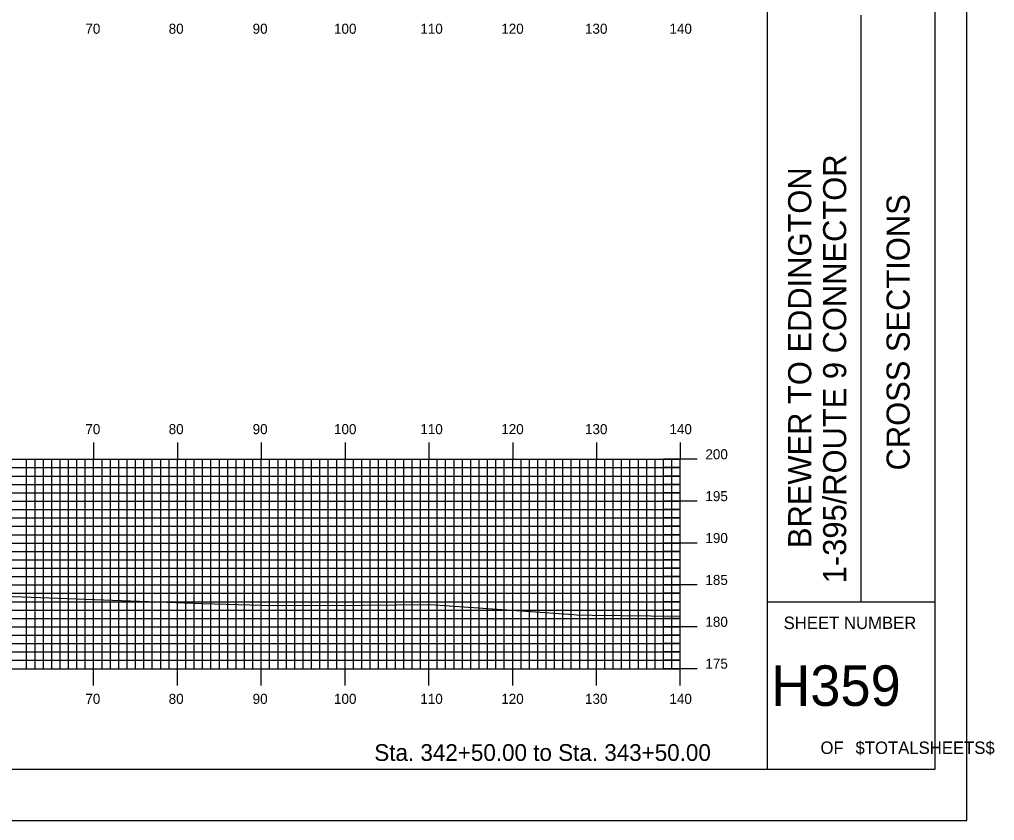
# Model space of a CAD drawing. Extents: x 1825147 to 1825490, y 442591 to 442811.
# Drawn here: x 1825373.5 to 1825489.9, y 442590.5 to 442686.2 of the extents above; entities that cross this region are included whole.
import ezdxf

# ---------------------------------------------------------------- set-up
doc = ezdxf.new("R2010")
doc.units = 0
for name, color, linetype in [('BORDER', 7, 'Continuous'), ('H_V ANNOTATION', 7, 'Continuous'), ('MAJOR', 7, 'Continuous'), ('MINOR', 7, 'Continuous'), ('PLOT BOUNDARY', 7, 'Continuous'), ('S_Roadway_Centerline', 7, 'Continuous')]:
    doc.layers.add(name, color=color, linetype=linetype)

msp = doc.modelspace()

# ---------------------------------------------------------------- linework, layer by layer
at = {"layer": 'BORDER'}
for p, q in [((1825462.76, 442596.67), (1825462.76, 442806.67)), ((1825473.94, 442616.67), (1825473.94, 442686.67)), ((1825462.76, 442616.67), (1825482.76, 442616.67))]:
    msp.add_line(p, q, dxfattribs=at)
msp.add_lwpolyline([(1825162.76, 442596.67), (1825482.76, 442596.67), (1825482.76, 442806.67), (1825162.76, 442806.67)], close=True, dxfattribs=at)
at = {"layer": 'MAJOR'}
for p, q in [((1825382.36, 442635.67), (1825382.36, 442633.67)), ((1825392.36, 442635.67), (1825392.36, 442633.67)), ((1825402.36, 442635.67), (1825402.36, 442633.67)), ((1825412.36, 442635.67), (1825412.36, 442633.67)), ((1825422.36, 442635.67), (1825422.36, 442633.67)), ((1825432.36, 442635.67), (1825432.36, 442633.67)), ((1825442.36, 442635.67), (1825442.36, 442633.67)), ((1825452.36, 442635.67), (1825452.36, 442633.67)), ((1825172.36, 442633.67), (1825452.36, 442633.67)), ((1825172.36, 442633.67), (1825452.36, 442633.67)), ((1825382.36, 442608.67), (1825382.36, 442633.67)), ((1825392.36, 442608.67), (1825392.36, 442633.67)), ((1825402.36, 442608.67), (1825402.36, 442633.67)), ((1825412.36, 442608.67), (1825412.36, 442633.67)), ((1825422.36, 442608.67), (1825422.36, 442633.67)), ((1825432.36, 442608.67), (1825432.36, 442633.67)), ((1825442.36, 442608.67), (1825442.36, 442633.67)), ((1825454.37, 442633.67), (1825450.36, 442633.67)), ((1825452.36, 442608.67), (1825452.36, 442633.67)), ((1825452.36, 442608.67), (1825452.36, 442633.67)), ((1825172.36, 442628.67), (1825452.36, 442628.67)), ((1825454.37, 442628.67), (1825450.36, 442628.67)), ((1825172.36, 442623.67), (1825452.36, 442623.67)), ((1825454.37, 442623.67), (1825450.36, 442623.67)), ((1825172.36, 442618.67), (1825452.36, 442618.67)), ((1825454.37, 442618.67), (1825450.36, 442618.67)), ((1825172.36, 442613.67), (1825452.36, 442613.67)), ((1825454.37, 442613.67), (1825450.36, 442613.67)), ((1825172.36, 442608.67), (1825452.36, 442608.67)), ((1825172.36, 442608.67), (1825452.36, 442608.67)), ((1825382.36, 442606.66), (1825382.36, 442608.67)), ((1825392.36, 442606.66), (1825392.36, 442608.67)), ((1825402.36, 442606.66), (1825402.36, 442608.67)), ((1825412.36, 442606.66), (1825412.36, 442608.67)), ((1825422.36, 442606.66), (1825422.36, 442608.67)), ((1825432.36, 442606.66), (1825432.36, 442608.67)), ((1825442.36, 442606.66), (1825442.36, 442608.67)), ((1825454.37, 442608.67), (1825450.36, 442608.67)), ((1825452.36, 442606.66), (1825452.36, 442608.67))]:
    msp.add_line(p, q, dxfattribs=at)
at = {"layer": 'MINOR'}
for p, q in [((1825374.36, 442608.67), (1825374.36, 442633.67)), ((1825375.36, 442608.67), (1825375.36, 442633.67)), ((1825376.36, 442608.67), (1825376.36, 442633.67)), ((1825377.36, 442608.67), (1825377.36, 442633.67)), ((1825378.36, 442608.67), (1825378.36, 442633.67)), ((1825379.36, 442608.67), (1825379.36, 442633.67)), ((1825380.36, 442608.67), (1825380.36, 442633.67)), ((1825381.36, 442608.67), (1825381.36, 442633.67)), ((1825383.36, 442608.67), (1825383.36, 442633.67)), ((1825384.36, 442608.67), (1825384.36, 442633.67)), ((1825385.36, 442608.67), (1825385.36, 442633.67)), ((1825386.36, 442608.67), (1825386.36, 442633.67)), ((1825387.36, 442608.67), (1825387.36, 442633.67)), ((1825388.36, 442608.67), (1825388.36, 442633.67)), ((1825389.36, 442608.67), (1825389.36, 442633.67)), ((1825390.36, 442608.67), (1825390.36, 442633.67)), ((1825391.36, 442608.67), (1825391.36, 442633.67)), ((1825393.36, 442608.67), (1825393.36, 442633.67)), ((1825394.36, 442608.67), (1825394.36, 442633.67)), ((1825395.36, 442608.67), (1825395.36, 442633.67)), ((1825396.36, 442608.67), (1825396.36, 442633.67)), ((1825397.36, 442608.67), (1825397.36, 442633.67)), ((1825398.36, 442608.67), (1825398.36, 442633.67)), ((1825399.36, 442608.67), (1825399.36, 442633.67)), ((1825400.36, 442608.67), (1825400.36, 442633.67)), ((1825401.36, 442608.67), (1825401.36, 442633.67)), ((1825403.36, 442608.67), (1825403.36, 442633.67)), ((1825404.36, 442608.67), (1825404.36, 442633.67)), ((1825405.36, 442608.67), (1825405.36, 442633.67)), ((1825406.36, 442608.67), (1825406.36, 442633.67)), ((1825407.36, 442608.67), (1825407.36, 442633.67)), ((1825408.36, 442608.67), (1825408.36, 442633.67)), ((1825409.36, 442608.67), (1825409.36, 442633.67)), ((1825410.36, 442608.67), (1825410.36, 442633.67)), ((1825411.36, 442608.67), (1825411.36, 442633.67)), ((1825413.36, 442608.67), (1825413.36, 442633.67)), ((1825414.36, 442608.67), (1825414.36, 442633.67)), ((1825415.36, 442608.67), (1825415.36, 442633.67)), ((1825416.36, 442608.67), (1825416.36, 442633.67)), ((1825417.36, 442608.67), (1825417.36, 442633.67)), ((1825418.36, 442608.67), (1825418.36, 442633.67)), ((1825419.36, 442608.67), (1825419.36, 442633.67)), ((1825420.36, 442608.67), (1825420.36, 442633.67)), ((1825421.36, 442608.67), (1825421.36, 442633.67)), ((1825423.36, 442608.67), (1825423.36, 442633.67)), ((1825424.36, 442608.67), (1825424.36, 442633.67)), ((1825425.36, 442608.67), (1825425.36, 442633.67)), ((1825426.36, 442608.67), (1825426.36, 442633.67)), ((1825427.36, 442608.67), (1825427.36, 442633.67)), ((1825428.36, 442608.67), (1825428.36, 442633.67)), ((1825429.36, 442608.67), (1825429.36, 442633.67)), ((1825430.36, 442608.67), (1825430.36, 442633.67)), ((1825431.36, 442608.67), (1825431.36, 442633.67)), ((1825433.36, 442608.67), (1825433.36, 442633.67)), ((1825434.36, 442608.67), (1825434.36, 442633.67)), ((1825435.36, 442608.67), (1825435.36, 442633.67)), ((1825436.36, 442608.67), (1825436.36, 442633.67)), ((1825437.36, 442608.67), (1825437.36, 442633.67)), ((1825438.36, 442608.67), (1825438.36, 442633.67)), ((1825439.36, 442608.67), (1825439.36, 442633.67)), ((1825440.36, 442608.67), (1825440.36, 442633.67)), ((1825441.36, 442608.67), (1825441.36, 442633.67)), ((1825443.36, 442608.67), (1825443.36, 442633.67)), ((1825444.36, 442608.67), (1825444.36, 442633.67)), ((1825445.36, 442608.67), (1825445.36, 442633.67)), ((1825446.36, 442608.67), (1825446.36, 442633.67)), ((1825447.36, 442608.67), (1825447.36, 442633.67)), ((1825448.36, 442608.67), (1825448.36, 442633.67)), ((1825449.36, 442608.67), (1825449.36, 442633.67)), ((1825450.36, 442608.67), (1825450.36, 442633.67)), ((1825451.36, 442608.67), (1825451.36, 442633.67)), ((1825172.36, 442632.67), (1825452.36, 442632.67)), ((1825452.36, 442632.67), (1825450.36, 442632.67)), ((1825172.36, 442631.67), (1825452.36, 442631.67)), ((1825452.36, 442631.67), (1825450.36, 442631.67)), ((1825172.36, 442630.67), (1825452.36, 442630.67)), ((1825452.36, 442630.67), (1825450.36, 442630.67)), ((1825172.36, 442629.67), (1825452.36, 442629.67)), ((1825452.36, 442629.67), (1825450.36, 442629.67)), ((1825172.36, 442627.67), (1825452.36, 442627.67)), ((1825452.36, 442627.67), (1825450.36, 442627.67)), ((1825172.36, 442626.67), (1825452.36, 442626.67)), ((1825452.36, 442626.67), (1825450.36, 442626.67)), ((1825172.36, 442625.67), (1825452.36, 442625.67)), ((1825452.36, 442625.67), (1825450.36, 442625.67)), ((1825172.36, 442624.67), (1825452.36, 442624.67)), ((1825452.36, 442624.67), (1825450.36, 442624.67)), ((1825172.36, 442622.67), (1825452.36, 442622.67)), ((1825452.36, 442622.67), (1825450.36, 442622.67)), ((1825172.36, 442621.67), (1825452.36, 442621.67)), ((1825172.36, 442620.67), (1825452.36, 442620.67)), ((1825452.36, 442621.67), (1825450.36, 442621.67)), ((1825452.36, 442620.67), (1825450.36, 442620.67)), ((1825172.36, 442619.67), (1825452.36, 442619.67)), ((1825452.36, 442619.67), (1825450.36, 442619.67)), ((1825172.36, 442617.67), (1825452.36, 442617.67)), ((1825452.36, 442617.67), (1825450.36, 442617.67)), ((1825172.36, 442616.67), (1825452.36, 442616.67)), ((1825452.36, 442616.67), (1825450.36, 442616.67)), ((1825172.36, 442615.67), (1825452.36, 442615.67)), ((1825452.36, 442615.67), (1825450.36, 442615.67)), ((1825172.36, 442614.67), (1825452.36, 442614.67)), ((1825452.36, 442614.67), (1825450.36, 442614.67)), ((1825172.36, 442612.67), (1825452.36, 442612.67)), ((1825452.36, 442612.67), (1825450.36, 442612.67)), ((1825172.36, 442611.67), (1825452.36, 442611.67)), ((1825452.36, 442611.67), (1825450.36, 442611.67)), ((1825172.36, 442610.67), (1825452.36, 442610.67)), ((1825452.36, 442610.67), (1825450.36, 442610.67)), ((1825172.36, 442609.67), (1825452.36, 442609.67)), ((1825452.36, 442609.67), (1825450.36, 442609.67))]:
    msp.add_line(p, q, dxfattribs=at)
at = {"layer": 'PLOT BOUNDARY'}
msp.add_lwpolyline([(1825146.57, 442590.55), (1825486.57, 442590.55), (1825486.57, 442810.55), (1825146.57, 442810.55)], close=True, dxfattribs=at)
at = {"layer": 'S_Roadway_Centerline'}
msp.add_lwpolyline([(1825364.09, 442617.59), (1825395.4, 442616.46), (1825402.38, 442616.27), (1825410.39, 442616.21), (1825422.56, 442616.35), (1825439.61, 442615.14), (1825439.99, 442615.12), (1825441.86, 442615.08), (1825452.36, 442614.93)], dxfattribs=at)

# ---------------------------------------------------------------- texts
at = {"layer": 'BORDER'}
for s, p in [('1-395/ROUTE 9 CONNECTOR', (1825472.16, 442618.87)), ('BREWER TO EDDINGTON', (1825467.99, 442623.07)), ('CROSS SECTIONS', (1825479.73, 442632.34))]:
    msp.add_text(s, height=2.7557, rotation=90, dxfattribs=at).set_placement(p)
for s, height, p in [('SHEET NUMBER', 1.4905, (1825464.69, 442613.4)), ('H359', 4.839, (1825463.2, 442604.23)), ('OF', 1.491, (1825469.09, 442598.49)), ('$TOTALSHEETS$', 1.4905, (1825473.27, 442598.49))]:
    msp.add_text(s, height=height, dxfattribs=at).set_placement(p)
at = {"layer": 'H_V ANNOTATION'}
for s, height, p in [('70', 1.2, (1825381.37, 442684.47)), ('80', 1.2, (1825391.31, 442684.47)), ('90', 1.2, (1825401.33, 442684.47)), ('100', 1.2, (1825411.04, 442684.47)), ('110', 1.2, (1825421.34, 442684.47)), ('120', 1.2, (1825431, 442684.47)), ('130', 1.2, (1825440.99, 442684.47)), ('140', 1.2, (1825451.07, 442684.47)), ('70', 1.2, (1825381.37, 442636.67)), ('80', 1.2, (1825391.31, 442636.67)), ('90', 1.2, (1825401.33, 442636.67)), ('100', 1.2, (1825411.04, 442636.67)), ('110', 1.2, (1825421.34, 442636.67)), ('120', 1.2, (1825431, 442636.67)), ('130', 1.2, (1825440.99, 442636.67)), ('140', 1.2, (1825451.07, 442636.67)), ('200', 1.2, (1825455.36, 442633.67)), ('195', 1.2, (1825455.36, 442628.67)), ('190', 1.2, (1825455.36, 442623.67)), ('185', 1.2, (1825455.36, 442618.67)), ('180', 1.2, (1825455.36, 442613.67)), ('175', 1.2, (1825455.36, 442608.67)), ('70', 1.2, (1825381.37, 442604.47)), ('80', 1.2, (1825391.31, 442604.47)), ('90', 1.2, (1825401.33, 442604.47)), ('100', 1.2, (1825411.04, 442604.47)), ('110', 1.2, (1825421.34, 442604.47)), ('120', 1.2, (1825431, 442604.47)), ('130', 1.2, (1825440.99, 442604.47)), ('140', 1.2, (1825451.07, 442604.47)), ('Sta. 342+50.00 to Sta. 343+50.00', 2.0004, (1825415.85, 442597.66))]:
    msp.add_text(s, height=height, dxfattribs=at).set_placement(p)

doc.saveas('drawing.dxf')
